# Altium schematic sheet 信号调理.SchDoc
size A4
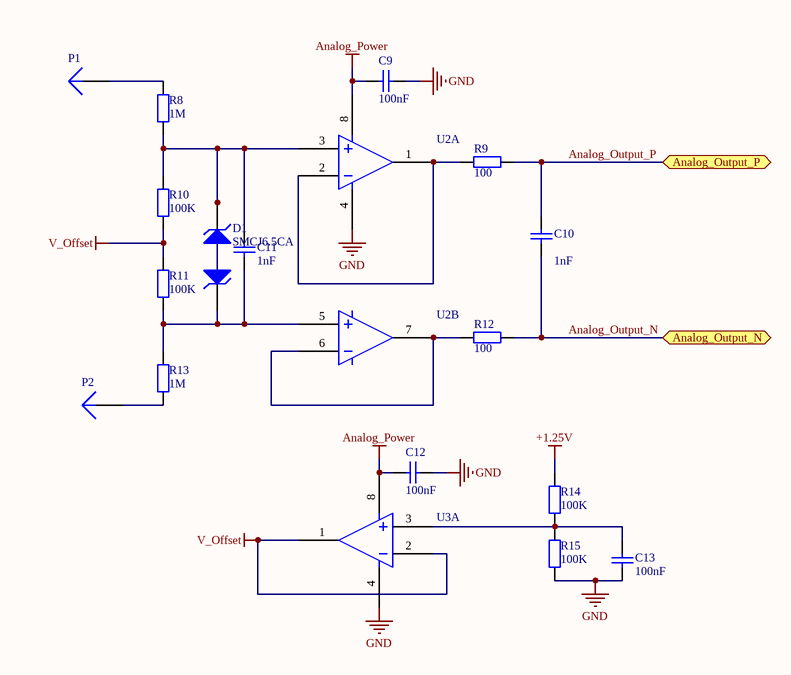
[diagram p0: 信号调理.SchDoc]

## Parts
C9  value 100nF  [0805C]
C10  value 1nF  [0805C]  (hidden comment: Cap)
C11  value 1nF  [0805C]
C12  value 100nF  [0805C]
C13  value 100nF  [0805C]
D1  SMCJ6.5CA  [DO-214AA]
P1  Plug  [PZ1]  (value not drawn)
P2  Plug  [PZ1]  (value not drawn)
R8  value 1M  [0805R]
R9  value 100  [0805R]
R10  value 100K  [0805R]
R11  value 100K  [0805R]
R12  value 100  [0805R]
R13  value 1M  [0805R]
R14  value 100K  [0805R]
R15  value 100K  [0805R]
U2  OPA2335  [SOP-8]  (value not drawn)  (parts A,B of 2)
U3  LM358  [SOP-8]  (value not drawn)  (part A of 2)

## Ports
Analog_Output_N, Analog_Output_P

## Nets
+1.25V: R14.1
Analog_Power: C9.1 C12.1 U2.8(VCC) U3.8(VCC)
GND: C9.2 C12.2 C13.1 R15.2 U2.4(VSS) U3.4(VSS)
V_Offset: R10.2 R11.1 U3.1(VOUT1) U3.2(VIN1-)
Analog_Output_N: C10.2 R12.2 ; port Analog_Output_N
Analog_Output_P: C10.1 R9.2 ; port Analog_Output_P
NetC11_1: C11.1 D1.1(K) R11.2 R13.1 U2.5(VIN1+)
NetC11_2: C11.2 D1.2(K) R8.2 R10.1 U2.3(VIN1+)
NetC13_2: C13.2 R14.2 R15.1 U3.3(VIN1+)
NetP1_1: P1.1 R8.1
NetP2_1: P2.1 R13.2
NetR9_1: R9.1 U2.1(VOUT1) U2.2(VIN1-)
NetR12_1: R12.1 U2.6(VIN1-) U2.7(VOUT1)

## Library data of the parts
C9 C11-C13 = Cap: 瓷片电容
C10 = Cap: 贴片电容
D1 = DIODE_TVS: 双向TVS二极管 5V耐压
R8-R15 = Res2: 贴片电阻
U2 = OPA2335: 自归零CMOS运放
U3 = LM358: 运算放大器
